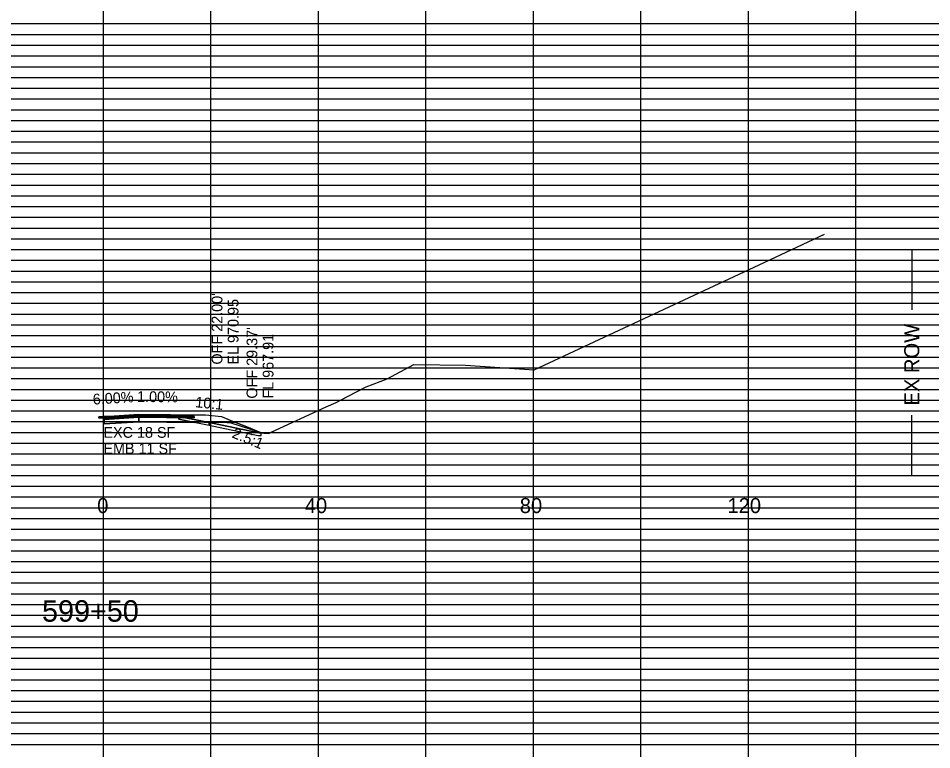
# Model space of a CAD drawing. Extents: x 2313580 to 2322968, y 282099 to 303247.
# Drawn here: x 2316394.2 to 2316564.2, y 287716.7 to 287852.7 of the extents above; entities that cross this region are included whole.
import ezdxf

# ---------------------------------------------------------------- set-up
doc = ezdxf.new("R2010")
doc.units = 0
for name, color, linetype in [('DESIGN - DRAINAGE - Text', 7, 'Continuous'), ('DESIGN - EARTHWORK - Excavation Limit Lines', 7, 'Continuous'), ('DESIGN - EARTHWORK - Shapes', 7, 'Continuous'), ('DESIGN - SCRATCH - User 5', 7, 'Continuous'), ('DESIGN - SHEET - Light Grid', 7, 'Continuous'), ('DESIGN - SHEET - Linework', 7, 'Continuous'), ('DESIGN - TYPICAL - Finished Grade and Subgrade', 7, 'Continuous'), ('DESIGN - TYPICAL - Finished Grade Slopes Text', 7, 'Continuous'), ('DESIGN - TYPICAL - Text', 7, 'Continuous'), ('Scratch Level', 7, 'Continuous'), ('SURVEY - GROUND - Top of Ground', 7, 'Continuous'), ('SURVEY - PROPERTY - ROW Lines Text', 7, 'Continuous')]:
    doc.layers.add(name, color=color, linetype=linetype)

msp = doc.modelspace()

# ---------------------------------------------------------------- linework, layer by layer
at = {"layer": 'DESIGN - EARTHWORK - Shapes'}
for points in [[(2316427.04, 287777.54), (2316424.1, 287778.12), (2316424.1, 287778.63), (2316422.26, 287779), (2316415.43, 287778.77), (2316410.06, 287778.65), (2316410.06, 287778.33), (2316410.23, 287778.34), (2316410.23, 287778.09), (2316410.23, 287777.26), (2316416.65, 287777.65)], [(2316429.77, 287777.52), (2316430.39, 287777.4), (2316438.97, 287775.61), (2316439.18, 287775.6), (2316439.45, 287775.58), (2316436.74, 287776.7), (2316434.87, 287777.47)]]:
    msp.add_lwpolyline(points, close=True, dxfattribs=at)
at = {"layer": 'DESIGN - SCRATCH - User 5'}
for points in [[(2316429.77, 287777.52), (2316424.1, 287778.63), (2316424.1, 287778.12), (2316429.77, 287777.01)], [(2316429.77, 287777.52), (2316424.1, 287778.63), (2316424.1, 287778.12), (2316429.77, 287777.01)], [(2316429.77, 287777.01), (2316430.29, 287776.91), (2316438.9, 287775.11), (2316439.15, 287775.1), (2316439.45, 287775.08), (2316439.45, 287775.58), (2316439.18, 287775.6), (2316438.97, 287775.61), (2316430.39, 287777.4), (2316429.77, 287777.52)], [(2316429.77, 287777.01), (2316430.29, 287776.91), (2316438.9, 287775.11), (2316439.15, 287775.1), (2316439.45, 287775.08), (2316439.45, 287775.58), (2316439.18, 287775.6), (2316438.97, 287775.61), (2316430.39, 287777.4), (2316429.77, 287777.52)]]:
    msp.add_lwpolyline(points, close=True, dxfattribs=at)
at = {"layer": 'DESIGN - SHEET - Light Grid'}
for p, q in [((2316250.08, 287851.67), (2316410.08, 287851.67)), ((2316410.08, 287851.67), (2316570.08, 287851.67)), ((2316250.08, 287849.67), (2316410.08, 287849.67)), ((2316410.08, 287849.67), (2316570.08, 287849.67)), ((2316250.08, 287845.67), (2316410.08, 287845.67)), ((2316410.08, 287845.67), (2316570.08, 287845.67)), ((2316250.08, 287843.67), (2316410.08, 287843.67)), ((2316410.08, 287843.67), (2316570.08, 287843.67)), ((2316250.08, 287841.67), (2316410.08, 287841.67)), ((2316410.08, 287841.67), (2316570.08, 287841.67)), ((2316250.08, 287839.67), (2316410.08, 287839.67)), ((2316410.08, 287839.67), (2316570.08, 287839.67)), ((2316250.08, 287837.67), (2316410.08, 287837.67)), ((2316410.08, 287837.67), (2316570.08, 287837.67)), ((2316250.08, 287835.67), (2316410.08, 287835.67)), ((2316410.08, 287835.67), (2316570.08, 287835.67)), ((2316250.08, 287833.67), (2316410.08, 287833.67)), ((2316410.08, 287833.67), (2316570.08, 287833.67)), ((2316250.08, 287831.67), (2316410.08, 287831.67)), ((2316410.08, 287831.67), (2316570.08, 287831.67)), ((2316250.08, 287829.67), (2316410.08, 287829.67)), ((2316410.08, 287829.67), (2316570.08, 287829.67)), ((2316250.08, 287825.67), (2316410.08, 287825.67)), ((2316410.08, 287825.67), (2316570.08, 287825.67)), ((2316250.08, 287823.67), (2316410.08, 287823.67)), ((2316410.08, 287823.67), (2316570.08, 287823.67)), ((2316250.08, 287821.67), (2316410.08, 287821.67)), ((2316410.08, 287821.67), (2316570.08, 287821.67)), ((2316250.08, 287819.67), (2316410.08, 287819.67)), ((2316410.08, 287819.67), (2316570.08, 287819.67)), ((2316250.08, 287817.67), (2316410.08, 287817.67)), ((2316410.08, 287817.67), (2316570.08, 287817.67)), ((2316250.08, 287815.67), (2316410.08, 287815.67)), ((2316410.08, 287815.67), (2316570.08, 287815.67)), ((2316250.08, 287813.67), (2316410.08, 287813.67)), ((2316410.08, 287813.67), (2316570.08, 287813.67)), ((2316250.08, 287811.67), (2316410.08, 287811.67)), ((2316410.08, 287811.67), (2316570.08, 287811.67)), ((2316250.08, 287809.67), (2316410.08, 287809.67)), ((2316410.08, 287809.67), (2316570.08, 287809.67)), ((2316250.08, 287805.67), (2316410.08, 287805.67)), ((2316410.08, 287805.67), (2316570.08, 287805.67)), ((2316250.08, 287803.67), (2316410.08, 287803.67)), ((2316410.08, 287803.67), (2316570.08, 287803.67)), ((2316250.08, 287801.67), (2316410.08, 287801.67)), ((2316410.08, 287801.67), (2316570.08, 287801.67)), ((2316250.08, 287799.67), (2316410.08, 287799.67)), ((2316410.08, 287799.67), (2316570.08, 287799.67)), ((2316250.08, 287797.67), (2316410.08, 287797.67)), ((2316410.08, 287797.67), (2316570.08, 287797.67)), ((2316250.08, 287795.67), (2316410.08, 287795.67)), ((2316410.08, 287795.67), (2316570.08, 287795.67)), ((2316250.08, 287793.67), (2316410.08, 287793.67)), ((2316410.08, 287793.67), (2316570.08, 287793.67)), ((2316250.08, 287791.67), (2316410.08, 287791.67)), ((2316410.08, 287791.67), (2316570.08, 287791.67)), ((2316250.08, 287789.67), (2316410.08, 287789.67)), ((2316410.08, 287789.67), (2316570.08, 287789.67)), ((2316250.08, 287785.67), (2316410.08, 287785.67)), ((2316410.08, 287785.67), (2316570.08, 287785.67)), ((2316250.08, 287783.67), (2316410.08, 287783.67)), ((2316410.08, 287783.67), (2316570.08, 287783.67)), ((2316250.08, 287781.67), (2316410.08, 287781.67)), ((2316410.08, 287781.67), (2316570.08, 287781.67)), ((2316250.08, 287779.67), (2316410.08, 287779.67)), ((2316410.08, 287779.67), (2316570.08, 287779.67)), ((2316250.08, 287777.67), (2316410.08, 287777.67)), ((2316410.08, 287777.67), (2316570.08, 287777.67)), ((2316250.08, 287775.67), (2316410.08, 287775.67)), ((2316410.08, 287775.67), (2316570.08, 287775.67)), ((2316250.08, 287773.67), (2316410.08, 287773.67)), ((2316410.08, 287773.67), (2316570.08, 287773.67)), ((2316250.08, 287771.67), (2316410.08, 287771.67)), ((2316410.08, 287771.67), (2316570.08, 287771.67)), ((2316250.08, 287769.67), (2316410.08, 287769.67)), ((2316410.08, 287769.67), (2316570.08, 287769.67)), ((2316250.08, 287765.67), (2316410.08, 287765.67)), ((2316410.08, 287765.67), (2316570.08, 287765.67)), ((2316250.08, 287763.67), (2316410.08, 287763.67)), ((2316410.08, 287763.67), (2316570.08, 287763.67)), ((2316250.08, 287761.67), (2316410.08, 287761.67)), ((2316410.08, 287761.67), (2316570.08, 287761.67)), ((2316250.08, 287759.67), (2316410.08, 287759.67)), ((2316410.08, 287759.67), (2316570.08, 287759.67)), ((2316250.08, 287757.67), (2316410.08, 287757.67)), ((2316410.08, 287757.67), (2316570.08, 287757.67)), ((2316250.08, 287755.67), (2316410.08, 287755.67)), ((2316410.08, 287755.67), (2316570.08, 287755.67)), ((2316250.08, 287753.67), (2316410.08, 287753.67)), ((2316410.08, 287753.67), (2316570.08, 287753.67)), ((2316250.08, 287751.67), (2316410.08, 287751.67)), ((2316410.08, 287751.67), (2316570.08, 287751.67)), ((2316250.08, 287749.67), (2316410.08, 287749.67)), ((2316410.08, 287749.67), (2316570.08, 287749.67)), ((2316250.08, 287745.67), (2316410.08, 287745.67)), ((2316410.08, 287745.67), (2316570.08, 287745.67)), ((2316250.08, 287743.67), (2316410.08, 287743.67)), ((2316410.08, 287743.67), (2316570.08, 287743.67)), ((2316250.08, 287741.67), (2316410.08, 287741.67)), ((2316410.08, 287741.67), (2316570.08, 287741.67)), ((2316250.08, 287739.67), (2316410.08, 287739.67)), ((2316410.08, 287739.67), (2316570.08, 287739.67)), ((2316250.08, 287737.67), (2316410.08, 287737.67)), ((2316410.08, 287737.67), (2316570.08, 287737.67)), ((2316250.08, 287735.67), (2316410.08, 287735.67)), ((2316410.08, 287735.67), (2316570.08, 287735.67)), ((2316250.08, 287733.67), (2316410.08, 287733.67)), ((2316410.08, 287733.67), (2316570.08, 287733.67)), ((2316250.08, 287731.67), (2316410.08, 287731.67)), ((2316410.08, 287731.67), (2316570.08, 287731.67)), ((2316250.08, 287729.67), (2316410.08, 287729.67)), ((2316410.08, 287729.67), (2316570.08, 287729.67)), ((2316250.08, 287725.67), (2316410.08, 287725.67)), ((2316410.08, 287725.67), (2316570.08, 287725.67)), ((2316250.08, 287723.67), (2316410.08, 287723.67)), ((2316410.08, 287723.67), (2316570.08, 287723.67)), ((2316250.08, 287721.67), (2316410.08, 287721.67)), ((2316410.08, 287721.67), (2316570.08, 287721.67)), ((2316250.08, 287719.67), (2316410.08, 287719.67)), ((2316410.08, 287719.67), (2316570.08, 287719.67)), ((2316250.08, 287717.67), (2316410.08, 287717.67)), ((2316410.08, 287717.67), (2316570.08, 287717.67))]:
    msp.add_line(p, q, dxfattribs=at)
at = {"layer": 'DESIGN - SHEET - Linework'}
for p, q in [((2316410.08, 287587.67), (2316410.08, 288007.67)), ((2316430.08, 287587.67), (2316430.08, 288007.67)), ((2316450.08, 287587.67), (2316450.08, 288007.67)), ((2316470.08, 287587.67), (2316470.08, 288007.67)), ((2316490.08, 287587.67), (2316490.08, 288007.67)), ((2316510.08, 287587.67), (2316510.08, 288007.67)), ((2316530.08, 287587.67), (2316530.08, 288007.67)), ((2316550.08, 287587.67), (2316550.08, 288007.67)), ((2316090.08, 287847.67), (2316730.08, 287847.67)), ((2316090.08, 287827.67), (2316730.08, 287827.67)), ((2316090.08, 287807.67), (2316730.08, 287807.67)), ((2316090.08, 287787.67), (2316730.08, 287787.67)), ((2316090.08, 287767.67), (2316730.08, 287767.67)), ((2316090.08, 287747.67), (2316730.08, 287747.67)), ((2316090.08, 287727.67), (2316730.08, 287727.67))]:
    msp.add_line(p, q, dxfattribs=at)
at = {"layer": 'DESIGN - TYPICAL - Finished Grade and Subgrade'}
msp.add_lwpolyline([(2316409.21, 287778.59), (2316409.35, 287778.6), (2316410.23, 287778.65), (2316415.81, 287778.99), (2316416.65, 287779.04), (2316425.44, 287778.95), (2316426.65, 287778.94), (2316428.41, 287778.92), (2316429.1, 287778.92), (2316432.08, 287778.62), (2316433.81, 287777.9), (2316436.74, 287776.7), (2316439.45, 287775.58)], dxfattribs=at)
for points in [[(2316410.23, 287778.65), (2316409.21, 287778.59), (2316409.21, 287778.49), (2316410.23, 287778.55)], [(2316410.23, 287778.55), (2316410.23, 287778.34), (2316409.21, 287778.29), (2316409.21, 287778.49)], [(2316410.23, 287778.65), (2316416.65, 287779.04), (2316416.65, 287778.94), (2316410.23, 287778.55)], [(2316410.23, 287778.55), (2316416.65, 287778.94), (2316416.65, 287778.73), (2316410.23, 287778.34)], [(2316410.23, 287778.34), (2316416.65, 287778.73), (2316416.65, 287778.48), (2316410.23, 287778.09)], [(2316410.23, 287778.09), (2316416.65, 287778.48), (2316416.65, 287777.65), (2316410.23, 287777.26)], [(2316416.65, 287779.04), (2316426.65, 287778.94), (2316426.65, 287778.84), (2316416.65, 287778.94)], [(2316416.65, 287778.94), (2316426.75, 287778.84), (2316426.75, 287778.64), (2316416.65, 287778.73)], [(2316416.65, 287778.48), (2316426.96, 287778.39), (2316426.96, 287778.64), (2316426.75, 287778.64), (2316426.75, 287778.84), (2316426.65, 287778.84), (2316426.65, 287778.94), (2316429.1, 287778.92), (2316432.08, 287778.62), (2316434.87, 287777.47), (2316416.65, 287777.65)], [(2316416.65, 287778.73), (2316426.96, 287778.64), (2316426.96, 287778.39), (2316416.65, 287778.48)]]:
    msp.add_lwpolyline(points, close=True, dxfattribs=at)
at = {"layer": 'Scratch Level'}
for points in [[(2316427.04, 287777.54), (2316424.1, 287778.12), (2316424.1, 287778.63), (2316422.26, 287779), (2316415.43, 287778.77), (2316410.06, 287778.65), (2316410.06, 287778.33), (2316410.23, 287778.34), (2316410.23, 287778.09), (2316410.23, 287777.26), (2316416.65, 287777.65)], [(2316429.77, 287777.52), (2316430.39, 287777.4), (2316438.97, 287775.61), (2316439.18, 287775.6), (2316439.45, 287775.58), (2316433.87, 287777.38), (2316433.55, 287777.48), (2316433.12, 287777.48)]]:
    msp.add_lwpolyline(points, close=True, dxfattribs=at)
at = {"layer": 'SURVEY - GROUND - Top of Ground'}
msp.add_lwpolyline([(2316410.06, 287778.65), (2316415.43, 287778.77), (2316422.26, 287779), (2316430.39, 287777.4), (2316438.97, 287775.61), (2316439.18, 287775.6), (2316439.55, 287775.57), (2316439.9, 287775.55), (2316440.28, 287775.52), (2316440.84, 287775.48), (2316441.3, 287775.7), (2316451.55, 287780.4), (2316453.4, 287781.25), (2316455.52, 287782.35), (2316458.99, 287784.15), (2316462.87, 287785.61), (2316467.84, 287788.32), (2316477.45, 287788.19), (2316490.25, 287787.31), (2316532.09, 287806.82), (2316544.26, 287812.53)], dxfattribs=at)
at = {"layer": 'SURVEY - PROPERTY - ROW Lines Text'}
for p, q in [((2316560.48, 287809.67), (2316560.48, 287798.47)), ((2316560.48, 287767.67), (2316560.48, 287778.87))]:
    msp.add_line(p, q, dxfattribs=at)

# ---------------------------------------------------------------- texts
at = {"layer": 'DESIGN - DRAINAGE - Text'}
for s, p in [("OFF 22.00'", (2316432.22, 287788.28)), ('EL 970.95', (2316435.22, 287788.28)), ("OFF 29.37'", (2316438.72, 287781.95)), ('FL 967.91', (2316441.72, 287781.95))]:
    msp.add_text(s, height=2, rotation=90, dxfattribs=at).set_placement(p)
at = {"layer": 'DESIGN - EARTHWORK - Excavation Limit Lines'}
for s, p in [('EXC 18 SF', (2316410.08, 287774.67)), ('EMB 11 SF', (2316410.08, 287771.67))]:
    msp.add_text(s, height=2, dxfattribs=at).set_placement(p)
at = {"layer": 'DESIGN - TYPICAL - Finished Grade Slopes Text'}
for s, rotation, p in [('6.00%', 3.4346, (2316408.16, 287780.83)), ('1.00%', 359.4286, (2316416.34, 287781.34)), ('10:1', 354.2894, (2316427.11, 287780.36)), ('2.5:1', 337.5981, (2316433.85, 287774.78))]:
    msp.add_text(s, height=2, rotation=rotation, dxfattribs=at).set_placement(p)
at = {"layer": 'DESIGN - TYPICAL - Text'}
for s, height, p in [('0', 2.8, (2316408.92, 287760.67)), ('40', 2.8, (2316447.55, 287760.67)), ('80', 2.8, (2316487.55, 287760.67)), ('120', 2.8, (2316526.19, 287760.67)), ('599+50', 4, (2316398.66, 287740.47))]:
    msp.add_text(s, height=height, dxfattribs=at).set_placement(p)
at = {"layer": 'SURVEY - PROPERTY - ROW Lines Text'}
msp.add_text('EX ROW', height=2.8, rotation=90, dxfattribs=at).set_placement((2316561.88, 287780.67))

doc.saveas('drawing.dxf')
